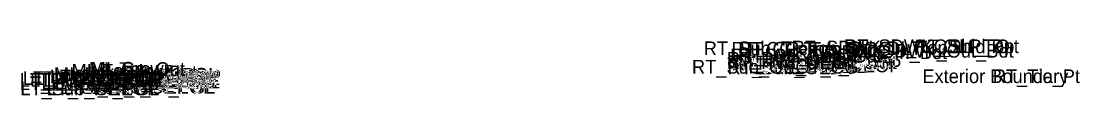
# Model space of a CAD drawing. Extents: x -26 to 6300, y -10 to 9528.
# Drawn here: x 3130.1 to 3207.7, y 2001.2 to 2005.6 of the extents above; entities that cross this region are included whole.
import ezdxf

# ---------------------------------------------------------------- set-up
doc = ezdxf.new("R2010")
doc.units = 0
doc.layers.add('Default', color=7, linetype='Continuous')

msp = doc.modelspace()

# ---------------------------------------------------------------- texts
at = {"layer": 'Default'}
for s, p in [('RT_Sub_Trench_Out_DLT', (3180.181, 2004.392)), ('RT_CG_Top_Face', (3182.225, 2004.353)), ('RT_CG_Top_BOC', (3182.694, 2004.353)), ('RT_SDWK_In_Top', (3186.62, 2004.443)), ('RT_SDWK_Out_Top', (3190.462, 2004.543)), ('RT_Shld_O', (3195.632, 2004.533)), ('CSLP_Pnt', (3197.035, 2004.543)), ('RT_PV2_OEOT', (3181.873, 2003.623)), ('RT_PV1_OEOT', (3182.112, 2003.873)), ('RT_CG_Top_Gut', (3182.752, 2003.853)), ('RT_SDWK_In_Bot', (3186.869, 2004.109)), ('RT_SDWK_Out_Bot', (3190.711, 2004.209)), ('MI_Top In', (3133.839, 2002.752)), ('MI_Top Out', (3135.095, 2002.872)), ('MI_Crown', (3135.239, 2002.896)), ('RT_Sub_OEOT_CG', (3179.318, 2003.039)), ('RT_PV3_OEOT', (3181.873, 2003.373)), ('RT_Sub_OEOT', (3181.92, 2002.998)), ('RT_CG_Bot_IE', (3182.221, 2003.289)), ('RT_CG1_Shelf_Out', (3182.36, 2003.379)), ('RT_CG_Bot_BOC', (3182.97, 2003.364)), ('RT_Sub_OEOP', (3185.154, 2003.136)), ('LT_PV2_OEEOP', (3130.035, 2002.085)), ('LT_PV1_OEEOP', (3130.275, 2002.21)), ('LT_PV2_IEEOP', (3130.796, 2002.085)), ('LT_PV1_IEEOP', (3131.035, 2002.21)), ('LT_PV2_PGL1', (3131.635, 2002.085)), ('LT_PV2_PGL', (3132.014, 2002.085)), ('LT_PV1_PGL', (3132.253, 2002.335)), ('MI_Face In', (3132.551, 2002.502)), ('MI_Bot In', (3133.721, 2002.335)), ('RT_PV2_OEEOP', (3133.917, 2002.205)), ('RT_PV3_OEEOP', (3133.917, 2001.955)), ('RT_PV1_OEEOP', (3134.157, 2002.33)), ('RT_PV2_IEEOP', (3134.678, 2002.205)), ('RT_PV1_IEEOP', (3134.917, 2002.33)), ('MI_Face Out', (3135.307, 2002.622)), ('RT_PV2_PGL1', (3135.516, 2002.205)), ('RT_PV3_PGL1', (3135.516, 2001.955)), ('RT_PV2_PGL', (3135.895, 2002.205)), ('RT_PV1_PGL', (3136.135, 2002.455)), ('MI_Bot Out', (3136.498, 2002.455)), ('Exterior Boundary', (3196.205, 2002.351)), ('RT_Tie_Pt', (3201.368, 2002.351)), ('LT_PV3_OEEOP', (3130.035, 2001.835)), ('LT_Sub_OEEOP', (3130.082, 2001.46)), ('LT_PV3_PGL1', (3131.635, 2001.835)), ('LT_PV4_PGL', (3132.014, 2001.46)), ('RT_Sub_OEEOP', (3133.964, 2001.58)), ('RT_PV4_PGL', (3135.895, 2001.58))]:
    msp.add_text(s, height=1, dxfattribs=at).set_placement(p)

doc.saveas('drawing.dxf')
